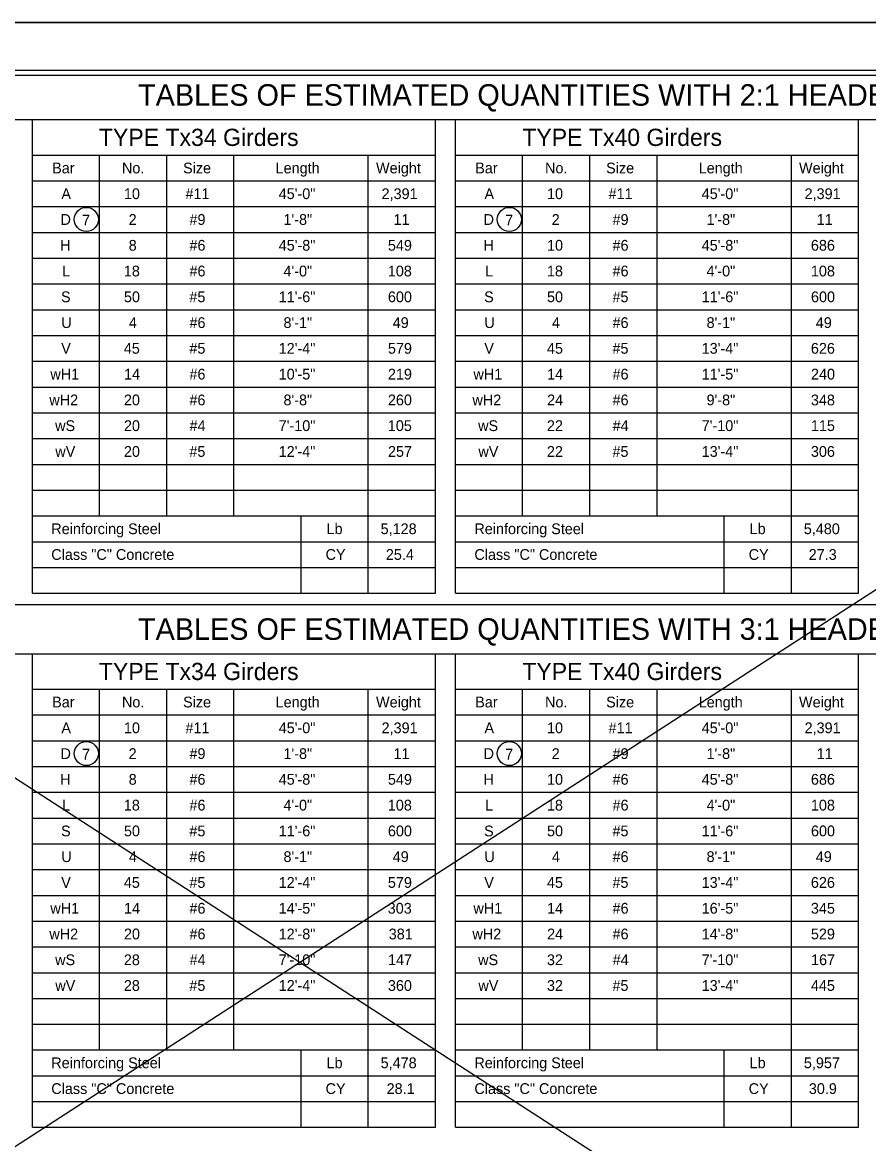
# Model space of a CAD drawing. Extents: x 926 to 1074, y 990 to 1081.
# Drawn here: x 1013.75 to 1023.65, y 1031.88 to 1045 of the extents above; entities that cross this region are included whole.
import ezdxf

# ---------------------------------------------------------------- set-up
doc = ezdxf.new("R2010")
doc.units = 0
for name, color, linetype in [('BORD_lines_major', 7, 'Continuous'), ('D_BATCH_PLOT', 7, 'Continuous'), ('D_SHEET', 7, 'Continuous'), ('Working Level 1', 7, 'Continuous')]:
    doc.layers.add(name, color=color, linetype=linetype)

msp = doc.modelspace()

# ---------------------------------------------------------------- linework, layer by layer
at = {"layer": 'BORD_lines_major'}
msp.add_line((1002.413, 1044.382), (1033.5, 1044.382), dxfattribs=at)
at = {"layer": 'D_BATCH_PLOT'}
msp.add_lwpolyline([(1000, 1023), (1034, 1023), (1034, 1045), (1000, 1045)], close=True, dxfattribs=at)
at = {"layer": 'D_SHEET'}
msp.add_line((1000, 1045), (1034, 1045), dxfattribs=at)
at = {"layer": 'Working Level 1'}
for p, q in [((1000, 1023), (1034, 1045)), ((1000, 1045), (1034, 1023)), ((1008.919, 1044.44), (1033.44, 1044.44)), ((1008.919, 1043.862), (1033.44, 1043.862)), ((1013.87, 1038.319), (1013.87, 1043.862)), ((1018.587, 1038.319), (1018.587, 1043.862)), ((1018.821, 1038.319), (1018.821, 1043.862)), ((1023.538, 1038.319), (1023.538, 1043.862)), ((1013.87, 1043.447), (1018.587, 1043.447)), ((1014.656, 1039.224), (1014.656, 1043.447)), ((1015.442, 1039.224), (1015.442, 1043.447)), ((1016.229, 1039.224), (1016.229, 1043.447)), ((1017.801, 1038.319), (1017.801, 1043.447)), ((1018.821, 1043.447), (1023.538, 1043.447)), ((1019.607, 1039.224), (1019.607, 1043.447)), ((1020.393, 1039.224), (1020.393, 1043.447)), ((1021.18, 1039.224), (1021.18, 1043.447)), ((1022.752, 1038.319), (1022.752, 1043.447)), ((1013.87, 1043.145), (1018.587, 1043.145)), ((1015.442, 1039.224), (1015.442, 1043.145)), ((1016.229, 1039.224), (1016.229, 1043.145)), ((1018.821, 1043.145), (1023.538, 1043.145)), ((1020.393, 1039.224), (1020.393, 1043.145)), ((1021.18, 1039.224), (1021.18, 1043.145)), ((1013.87, 1042.844), (1018.587, 1042.844)), ((1018.821, 1042.844), (1023.538, 1042.844)), ((1013.87, 1042.542), (1018.587, 1042.542)), ((1018.821, 1042.542), (1023.538, 1042.542)), ((1013.87, 1042.24), (1018.587, 1042.24)), ((1018.821, 1042.24), (1023.538, 1042.24)), ((1013.87, 1041.939), (1018.587, 1041.939)), ((1018.821, 1041.939), (1023.538, 1041.939)), ((1013.87, 1041.637), (1018.587, 1041.637)), ((1018.821, 1041.637), (1023.538, 1041.637)), ((1013.87, 1041.336), (1018.587, 1041.336)), ((1018.821, 1041.336), (1023.538, 1041.336)), ((1013.87, 1041.034), (1018.587, 1041.034)), ((1018.821, 1041.034), (1023.538, 1041.034)), ((1013.87, 1040.732), (1018.587, 1040.732)), ((1018.821, 1040.732), (1023.538, 1040.732)), ((1013.87, 1040.431), (1018.587, 1040.431)), ((1018.821, 1040.431), (1023.538, 1040.431)), ((1013.87, 1040.129), (1018.587, 1040.129)), ((1018.821, 1040.129), (1023.538, 1040.129)), ((1013.87, 1039.827), (1018.587, 1039.827)), ((1018.821, 1039.827), (1023.538, 1039.827)), ((1013.87, 1039.526), (1018.587, 1039.526)), ((1018.821, 1039.526), (1023.538, 1039.526)), ((1013.87, 1039.224), (1018.587, 1039.224)), ((1017.015, 1038.319), (1017.015, 1039.224)), ((1018.821, 1039.224), (1023.538, 1039.224)), ((1021.966, 1038.319), (1021.966, 1039.224)), ((1013.87, 1038.922), (1018.587, 1038.922)), ((1018.821, 1038.922), (1023.538, 1038.922)), ((1013.87, 1038.621), (1018.587, 1038.621)), ((1018.821, 1038.621), (1023.538, 1038.621)), ((1013.87, 1038.319), (1018.587, 1038.319)), ((1018.821, 1038.319), (1023.538, 1038.319)), ((1008.919, 1038.188), (1033.44, 1038.188)), ((1008.919, 1037.61), (1033.44, 1037.61)), ((1013.87, 1032.068), (1013.87, 1037.61)), ((1018.587, 1032.068), (1018.587, 1037.61)), ((1018.821, 1032.068), (1018.821, 1037.61)), ((1023.538, 1032.068), (1023.538, 1037.61)), ((1013.87, 1037.195), (1018.587, 1037.195)), ((1014.656, 1032.972), (1014.656, 1037.195)), ((1015.442, 1032.972), (1015.442, 1037.195)), ((1016.229, 1032.972), (1016.229, 1037.195)), ((1017.801, 1032.068), (1017.801, 1037.195)), ((1018.821, 1037.195), (1023.538, 1037.195)), ((1019.607, 1032.972), (1019.607, 1037.195)), ((1020.393, 1032.972), (1020.393, 1037.195)), ((1021.18, 1032.972), (1021.18, 1037.195)), ((1022.752, 1032.068), (1022.752, 1037.195)), ((1013.87, 1036.894), (1018.587, 1036.894)), ((1015.442, 1032.972), (1015.442, 1036.894)), ((1016.229, 1032.972), (1016.229, 1036.894)), ((1018.821, 1036.894), (1023.538, 1036.894)), ((1020.393, 1032.972), (1020.393, 1036.894)), ((1021.18, 1032.972), (1021.18, 1036.894)), ((1013.87, 1036.592), (1018.587, 1036.592)), ((1018.821, 1036.592), (1023.538, 1036.592)), ((1013.87, 1036.291), (1018.587, 1036.291)), ((1018.821, 1036.291), (1023.538, 1036.291)), ((1013.87, 1035.989), (1018.587, 1035.989)), ((1018.821, 1035.989), (1023.538, 1035.989)), ((1013.87, 1035.687), (1018.587, 1035.687)), ((1018.821, 1035.687), (1023.538, 1035.687)), ((1013.87, 1035.386), (1018.587, 1035.386)), ((1018.821, 1035.386), (1023.538, 1035.386)), ((1013.87, 1035.084), (1018.587, 1035.084)), ((1018.821, 1035.084), (1023.538, 1035.084)), ((1013.87, 1034.782), (1018.587, 1034.782)), ((1018.821, 1034.782), (1023.538, 1034.782)), ((1013.87, 1034.481), (1018.587, 1034.481)), ((1018.821, 1034.481), (1023.538, 1034.481)), ((1013.87, 1034.179), (1018.587, 1034.179)), ((1018.821, 1034.179), (1023.538, 1034.179)), ((1013.87, 1033.877), (1018.587, 1033.877)), ((1018.821, 1033.877), (1023.538, 1033.877)), ((1013.87, 1033.576), (1018.587, 1033.576)), ((1018.821, 1033.576), (1023.538, 1033.576)), ((1013.87, 1033.274), (1018.587, 1033.274)), ((1018.821, 1033.274), (1023.538, 1033.274)), ((1013.87, 1032.972), (1018.587, 1032.972)), ((1017.015, 1032.068), (1017.015, 1032.972)), ((1018.821, 1032.972), (1023.538, 1032.972)), ((1021.966, 1032.068), (1021.966, 1032.972)), ((1013.87, 1032.671), (1018.587, 1032.671)), ((1018.821, 1032.671), (1023.538, 1032.671)), ((1013.87, 1032.369), (1018.587, 1032.369)), ((1018.821, 1032.369), (1023.538, 1032.369)), ((1013.87, 1032.068), (1018.587, 1032.068)), ((1018.821, 1032.068), (1023.538, 1032.068))]:
    msp.add_line(p, q, dxfattribs=at)
for centre in [(1014.501, 1042.694), (1019.451, 1042.694), (1014.501, 1036.442), (1019.451, 1036.442)]:
    msp.add_circle(centre, 0.141, dxfattribs=at)

# ---------------------------------------------------------------- texts
for s, height, p in [('TABLES OF ESTIMATED QUANTITIES WITH 2:1 HEADER SLOPE', 0.252, (1015.107, 1044.025)), ('TYPE Tx34 Girders ', 0.2016, (1014.648, 1043.554)), ('TYPE Tx40 Girders ', 0.2016, (1019.603, 1043.554)), ('Bar', 0.126, (1014.101, 1043.233)), ('No.', 0.126, (1014.918, 1043.233)), ('Size', 0.126, (1015.633, 1043.233)), ('Length', 0.126, (1016.716, 1043.233)), ('Weight', 0.126, (1017.891, 1043.233)), ('Bar', 0.126, (1019.052, 1043.233)), ('No.', 0.126, (1019.869, 1043.233)), ('Size', 0.126, (1020.584, 1043.233)), ('Length', 0.126, (1021.667, 1043.233)), ('Weight', 0.126, (1022.841, 1043.233)), ('A', 0.126, (1014.209, 1042.932)), ('10', 0.126, (1014.941, 1042.932)), ('#11', 0.126, (1015.661, 1042.932)), ('45\'-0"', 0.126, (1016.752, 1042.932)), ('2,391', 0.126, (1017.956, 1042.932)), ('A', 0.126, (1019.16, 1042.932)), ('10', 0.126, (1019.892, 1042.932)), ('#11', 0.126, (1020.612, 1042.932)), ('45\'-0"', 0.126, (1021.702, 1042.932)), ('2,391', 0.126, (1022.906, 1042.932)), ('D', 0.126, (1014.199, 1042.63)), ('7', 0.126, (1014.451, 1042.623)), ('2', 0.126, (1014.996, 1042.63)), ('#9', 0.126, (1015.708, 1042.63)), ('1\'-8"', 0.126, (1016.808, 1042.63)), ('11', 0.126, (1018.096, 1042.63)), ('D', 0.126, (1019.15, 1042.63)), ('7', 0.126, (1019.402, 1042.623)), ('2', 0.126, (1019.947, 1042.63)), ('#9', 0.126, (1020.659, 1042.63)), ('1\'-8"', 0.126, (1021.759, 1042.63)), ('11', 0.126, (1023.047, 1042.63)), ('H', 0.126, (1014.196, 1042.328)), ('8', 0.126, (1014.997, 1042.328)), ('#6', 0.126, (1015.708, 1042.328)), ('45\'-8"', 0.126, (1016.752, 1042.328)), ('549', 0.126, (1018.03, 1042.328)), ('H', 0.126, (1019.147, 1042.328)), ('10', 0.126, (1019.892, 1042.328)), ('#6', 0.126, (1020.659, 1042.328)), ('45\'-8"', 0.126, (1021.702, 1042.328)), ('686', 0.126, (1022.98, 1042.328)), ('L', 0.126, (1014.219, 1042.027)), ('18', 0.126, (1014.94, 1042.027)), ('#6', 0.126, (1015.708, 1042.027)), ('4\'-0"', 0.126, (1016.808, 1042.027)), ('108', 0.126, (1018.029, 1042.027)), ('L', 0.126, (1019.169, 1042.027)), ('18', 0.126, (1019.891, 1042.027)), ('#6', 0.126, (1020.659, 1042.027)), ('4\'-0"', 0.126, (1021.759, 1042.027)), ('108', 0.126, (1022.98, 1042.027)), ('S', 0.126, (1014.205, 1041.725)), ('50', 0.126, (1014.941, 1041.725)), ('#5', 0.126, (1015.707, 1041.725)), ('11\'-6"', 0.126, (1016.752, 1041.725)), ('600', 0.126, (1018.03, 1041.725)), ('S', 0.126, (1019.156, 1041.725)), ('50', 0.126, (1019.892, 1041.725)), ('#5', 0.126, (1020.658, 1041.725)), ('11\'-6"', 0.126, (1021.702, 1041.725)), ('600', 0.126, (1022.981, 1041.725)), ('U', 0.126, (1014.208, 1041.423)), ('4', 0.126, (1014.999, 1041.423)), ('#6', 0.126, (1015.708, 1041.423)), ('8\'-1"', 0.126, (1016.808, 1041.423)), ('49', 0.126, (1018.086, 1041.423)), ('U', 0.126, (1019.159, 1041.423)), ('4', 0.126, (1019.95, 1041.423)), ('#6', 0.126, (1020.659, 1041.423)), ('8\'-1"', 0.126, (1021.759, 1041.423)), ('49', 0.126, (1023.037, 1041.423)), ('V', 0.126, (1014.207, 1041.122)), ('45', 0.126, (1014.94, 1041.122)), ('#5', 0.126, (1015.707, 1041.122)), ('12\'-4"', 0.126, (1016.752, 1041.122)), ('579', 0.126, (1018.03, 1041.122)), ('V', 0.126, (1019.158, 1041.122)), ('45', 0.126, (1019.891, 1041.122)), ('#5', 0.126, (1020.658, 1041.122)), ('13\'-4"', 0.126, (1021.702, 1041.122)), ('626', 0.126, (1022.98, 1041.122)), ('wH1', 0.126, (1014.08, 1040.82)), ('14', 0.126, (1014.942, 1040.82)), ('#6', 0.126, (1015.708, 1040.82)), ('10\'-5"', 0.126, (1016.752, 1040.82)), ('219', 0.126, (1018.03, 1040.82)), ('wH1', 0.126, (1019.031, 1040.82)), ('14', 0.126, (1019.893, 1040.82)), ('#6', 0.126, (1020.659, 1040.82)), ('11\'-5"', 0.126, (1021.702, 1040.82)), ('240', 0.126, (1022.981, 1040.82)), ('wH2', 0.126, (1014.068, 1040.518)), ('20', 0.126, (1014.941, 1040.518)), ('#6', 0.126, (1015.708, 1040.518)), ('8\'-8"', 0.126, (1016.808, 1040.518)), ('260', 0.126, (1018.03, 1040.518)), ('wH2', 0.126, (1019.019, 1040.518)), ('24', 0.126, (1019.893, 1040.518)), ('#6', 0.126, (1020.659, 1040.518)), ('9\'-8"', 0.126, (1021.759, 1040.518)), ('348', 0.126, (1022.98, 1040.518)), ('wS', 0.126, (1014.136, 1040.217)), ('20', 0.126, (1014.941, 1040.217)), ('#4', 0.126, (1015.709, 1040.217)), ('7\'-10"', 0.126, (1016.752, 1040.217)), ('105', 0.126, (1018.029, 1040.217)), ('wS', 0.126, (1019.086, 1040.217)), ('22', 0.126, (1019.891, 1040.217)), ('#4', 0.126, (1020.66, 1040.217)), ('7\'-10"', 0.126, (1021.702, 1040.217)), ('115', 0.126, (1022.98, 1040.217)), ('wV', 0.126, (1014.138, 1039.915)), ('20', 0.126, (1014.941, 1039.915)), ('#5', 0.126, (1015.707, 1039.915)), ('12\'-4"', 0.126, (1016.752, 1039.915)), ('257', 0.126, (1018.031, 1039.915)), ('wV', 0.126, (1019.089, 1039.915)), ('22', 0.126, (1019.891, 1039.915)), ('#5', 0.126, (1020.658, 1039.915)), ('13\'-4"', 0.126, (1021.702, 1039.915)), ('306', 0.126, (1022.98, 1039.915)), ('Reinforcing Steel', 0.126, (1014.091, 1039.01)), ('Lb', 0.126, (1017.312, 1039.01)), ('5,128', 0.126, (1017.945, 1039.01)), ('Reinforcing Steel', 0.126, (1019.042, 1039.01)), ('Lb', 0.126, (1022.263, 1039.01)), ('5,480', 0.126, (1022.897, 1039.01)), ('Class "C" Concrete', 0.126, (1014.091, 1038.709)), ('CY', 0.126, (1017.301, 1038.709)), ('25.4', 0.126, (1018.006, 1038.709)), ('Class "C" Concrete', 0.126, (1019.042, 1038.709)), ('CY', 0.126, (1022.252, 1038.709)), ('27.3', 0.126, (1022.954, 1038.709)), ('TABLES OF ESTIMATED QUANTITIES WITH 3:1 HEADER SLOPE', 0.252, (1015.106, 1037.773)), ('TYPE Tx34 Girders ', 0.2016, (1014.648, 1037.302)), ('TYPE Tx40 Girders ', 0.2016, (1019.603, 1037.302)), ('Bar', 0.126, (1014.101, 1036.982)), ('No.', 0.126, (1014.918, 1036.982)), ('Size', 0.126, (1015.633, 1036.982)), ('Length', 0.126, (1016.716, 1036.982)), ('Weight', 0.126, (1017.891, 1036.982)), ('Bar', 0.126, (1019.052, 1036.982)), ('No.', 0.126, (1019.869, 1036.982)), ('Size', 0.126, (1020.584, 1036.982)), ('Length', 0.126, (1021.667, 1036.982)), ('Weight', 0.126, (1022.841, 1036.982)), ('A', 0.126, (1014.209, 1036.68)), ('10', 0.126, (1014.941, 1036.68)), ('#11', 0.126, (1015.661, 1036.68)), ('45\'-0"', 0.126, (1016.752, 1036.68)), ('2,391', 0.126, (1017.956, 1036.68)), ('A', 0.126, (1019.16, 1036.68)), ('10', 0.126, (1019.892, 1036.68)), ('#11', 0.126, (1020.612, 1036.68)), ('45\'-0"', 0.126, (1021.702, 1036.68)), ('2,391', 0.126, (1022.906, 1036.68)), ('D', 0.126, (1014.199, 1036.378)), ('7', 0.126, (1014.451, 1036.372)), ('2', 0.126, (1014.996, 1036.378)), ('#9', 0.126, (1015.708, 1036.378)), ('1\'-8"', 0.126, (1016.808, 1036.378)), ('11', 0.126, (1018.096, 1036.378)), ('D', 0.126, (1019.15, 1036.378)), ('7', 0.126, (1019.402, 1036.372)), ('2', 0.126, (1019.947, 1036.378)), ('#9', 0.126, (1020.659, 1036.378)), ('1\'-8"', 0.126, (1021.759, 1036.378)), ('11', 0.126, (1023.047, 1036.378)), ('H', 0.126, (1014.196, 1036.077)), ('8', 0.126, (1014.997, 1036.077)), ('#6', 0.126, (1015.708, 1036.077)), ('45\'-8"', 0.126, (1016.752, 1036.077)), ('549', 0.126, (1018.03, 1036.077)), ('H', 0.126, (1019.147, 1036.077)), ('10', 0.126, (1019.892, 1036.077)), ('#6', 0.126, (1020.659, 1036.077)), ('45\'-8"', 0.126, (1021.702, 1036.077)), ('686', 0.126, (1022.98, 1036.077)), ('L', 0.126, (1014.219, 1035.775)), ('18', 0.126, (1014.94, 1035.775)), ('#6', 0.126, (1015.708, 1035.775)), ('4\'-0"', 0.126, (1016.808, 1035.775)), ('108', 0.126, (1018.029, 1035.775)), ('L', 0.126, (1019.169, 1035.775)), ('18', 0.126, (1019.891, 1035.775)), ('#6', 0.126, (1020.659, 1035.775)), ('4\'-0"', 0.126, (1021.759, 1035.775)), ('108', 0.126, (1022.98, 1035.775)), ('S', 0.126, (1014.205, 1035.473)), ('50', 0.126, (1014.941, 1035.473)), ('#5', 0.126, (1015.707, 1035.473)), ('11\'-6"', 0.126, (1016.752, 1035.473)), ('600', 0.126, (1018.03, 1035.473)), ('S', 0.126, (1019.156, 1035.473)), ('50', 0.126, (1019.892, 1035.473)), ('#5', 0.126, (1020.658, 1035.473)), ('11\'-6"', 0.126, (1021.702, 1035.473)), ('600', 0.126, (1022.981, 1035.473)), ('#6', 0.126, (1015.708, 1035.172)), ('8\'-1"', 0.126, (1016.808, 1035.172)), ('49', 0.126, (1018.086, 1035.172)), ('#6', 0.126, (1020.659, 1035.172)), ('8\'-1"', 0.126, (1021.759, 1035.172)), ('49', 0.126, (1023.037, 1035.172)), ('U', 0.126, (1014.208, 1035.172)), ('4', 0.126, (1014.999, 1035.172)), ('U', 0.126, (1019.159, 1035.172)), ('4', 0.126, (1019.95, 1035.172)), ('V', 0.126, (1014.207, 1034.87)), ('45', 0.126, (1014.94, 1034.87)), ('#5', 0.126, (1015.707, 1034.87)), ('12\'-4"', 0.126, (1016.752, 1034.87)), ('579', 0.126, (1018.03, 1034.87)), ('V', 0.126, (1019.158, 1034.87)), ('45', 0.126, (1019.891, 1034.87)), ('#5', 0.126, (1020.658, 1034.87)), ('13\'-4"', 0.126, (1021.702, 1034.87)), ('626', 0.126, (1022.98, 1034.87)), ('wH1', 0.126, (1014.08, 1034.568)), ('14', 0.126, (1014.942, 1034.568)), ('#6', 0.126, (1015.708, 1034.568)), ('14\'-5"', 0.126, (1016.752, 1034.568)), ('303', 0.126, (1018.028, 1034.568)), ('wH1', 0.126, (1019.031, 1034.568)), ('14', 0.126, (1019.893, 1034.568)), ('#6', 0.126, (1020.659, 1034.568)), ('16\'-5"', 0.126, (1021.702, 1034.568)), ('345', 0.126, (1022.98, 1034.568)), ('wH2', 0.126, (1014.068, 1034.267)), ('20', 0.126, (1014.941, 1034.267)), ('#6', 0.126, (1015.708, 1034.267)), ('12\'-8"', 0.126, (1016.752, 1034.267)), ('381', 0.126, (1018.04, 1034.267)), ('wH2', 0.126, (1019.019, 1034.267)), ('24', 0.126, (1019.893, 1034.267)), ('#6', 0.126, (1020.659, 1034.267)), ('14\'-8"', 0.126, (1021.702, 1034.267)), ('529', 0.126, (1022.98, 1034.267)), ('wS', 0.126, (1014.136, 1033.965)), ('28', 0.126, (1014.94, 1033.965)), ('#4', 0.126, (1015.709, 1033.965)), ('7\'-10"', 0.126, (1016.752, 1033.965)), ('147', 0.126, (1018.031, 1033.965)), ('wS', 0.126, (1019.086, 1033.965)), ('32', 0.126, (1019.891, 1033.965)), ('#4', 0.126, (1020.66, 1033.965)), ('7\'-10"', 0.126, (1021.702, 1033.965)), ('167', 0.126, (1022.982, 1033.965)), ('wV', 0.126, (1014.138, 1033.664)), ('28', 0.126, (1014.94, 1033.664)), ('#5', 0.126, (1015.707, 1033.664)), ('12\'-4"', 0.126, (1016.752, 1033.664)), ('360', 0.126, (1018.03, 1033.664)), ('wV', 0.126, (1019.089, 1033.664)), ('32', 0.126, (1019.891, 1033.664)), ('#5', 0.126, (1020.658, 1033.664)), ('13\'-4"', 0.126, (1021.702, 1033.664)), ('445', 0.126, (1022.98, 1033.664)), ('Reinforcing Steel', 0.126, (1014.091, 1032.759)), ('Lb', 0.126, (1017.312, 1032.759)), ('5,478', 0.126, (1017.945, 1032.759)), ('Reinforcing Steel', 0.126, (1019.042, 1032.759)), ('Lb', 0.126, (1022.263, 1032.759)), ('5,957', 0.126, (1022.898, 1032.759)), ('Class "C" Concrete', 0.126, (1014.091, 1032.457)), ('CY', 0.126, (1017.301, 1032.457)), ('28.1', 0.126, (1018.015, 1032.457)), ('Class "C" Concrete', 0.126, (1019.042, 1032.457)), ('CY', 0.126, (1022.252, 1032.457)), ('30.9', 0.126, (1022.956, 1032.457))]:
    msp.add_text(s, height=height, dxfattribs=at).set_placement(p)

doc.saveas('drawing.dxf')
